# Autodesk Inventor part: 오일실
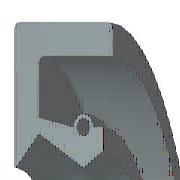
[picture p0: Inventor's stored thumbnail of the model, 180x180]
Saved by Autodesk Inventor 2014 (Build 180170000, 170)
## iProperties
Created: 2009-02
Part Number: 오일실
Material: 고무
Description: 오일-실
Document SubType Name: Modeling
Standard: KS B 2804
Designer: KYOUNG IL JANG
Standards Organization: KS
Language: ko-KR
Size Designation: D - 10 20 7
Categories: <MemberInstance><Categories><Category DisplayName="샤프트 부품" InternalName="7f7aeb1f-a693-4053-b835-cee3144e0d98" Mnemonic="SHFT"><Category DisplayName="실링" Intern
Density: 0.93 g/cm^3
Mass: 1.11329 g
Surface Area: 16.3871 cm^2
Volume: 1.19708 cm^3
Appearance: 고무 - 검은색 - 버전 1.1
Company: 한국ATC센터
IsCustomPart: 0
Author: KYOUNG IL JANG
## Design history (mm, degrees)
revolve "본체" stored, may be unused: angle "d17" = 90 deg
revolve "스프링1" stored, may be unused: angle "d18" = 90 deg
body "Solid1"
sketch "스케치1"
  geometry: L1 (0, 10)-(7, 10); L2 (7, 8.25)-(1.75, 8.25); L3 (1.75, 6.75)-(4.9, 5); L4 (4.9, 5)-(0, 5); L5 (0, 0)-(9.586, 0) reference; L6 (4.9, 5)-(6.3, 5.875); L7 (0, 18)-(0, -3) reference; L8 (-1.941, 0)-(11.507, 0) reference; L9 (4.2, 7.1)-(1.75, 7.59); L10 (1.75, 7.59)-(1.75, 8.25); L11 (0, 10)-(0, 5.088); L12 (4.9, 5)-(0, 5); L13 (1.75, 6.75)-(0.152, 5.028); L14 (7, 10)-(7, 8.25); L15 (5.6, 7.1)-(6.3, 7.1); L16 (6.3, 7.1)-(6.3, 5.875); C1 r 0.455 at (4.9, 7.1); A1 r 0.7 centre (4.9, 7.1) between (5.6, 7.1) and (4.2, 7.1); A2 r 0.088 centre (0.088, 5.088) between (0, 5.088) and (0.152, 5.028); 1 further point
  constraints: 28 end point, 5 horizontal alignment, 5 point on line, 4 point on circle, 4 vertical alignment, 3 centre point, 3 tangent, 2 collinear, 2 horizontal, 2 perpendicular, 1 coincident, 1 parallel
  dimensions: "d0" = 20 diameter of L1 L5 (= SD2); "d1" = 1.75 distance of L1.end L2.start (= SD); "d2" = 0.91 diameter of C1 (= SPDI); "d3" = 1.4 diameter of A1 (= SPDA); "d4" = 10 diameter of L3.end L5 (= NND); "d5" = 13.5 diameter of L3.start L5 (= TKDM); "d7" = 15.18 diameter of L9.end L5 (= TKDM + 0.24 x SWDT); "d8" = 1.75 distance between parallel lines of L11 L10 (= SD); "d9" = 4.9 distance from line of L11 C1.centre (= SPDST); "d10" = 14.2 diameter of C1.centre L5 (= HLDM); "d11" = 0.0875 radius of A2 (= 0.25 x LAB); "d12" = 6.3 distance between parallel lines of L11 L16 (= SDI); "d13" = 11.75 diameter of L6.end L5 (= ABDM); "d14" = 7 distance from line of L11 L1.end (= SWDT)
fillet "모깎기1" dims "d6" = 0.3 (= RR)
other parameters: "SD2" = 20 [user parameter; used in 1 equation term], "SWDT" = 7 [user parameter; used in 2 equation terms], "RR" = 0.3 [user parameter; used in 1 equation term], "SD" = 1.75 [user parameter; used in 2 equation terms], "NND" = 10 [user parameter; used in 1 equation term], "SPDA" = 1.4 [user parameter; used in 1 equation term], "SPDI" = 0.91 [user parameter; used in 1 equation term], "TKDM" = 13.5 [user parameter; used in 2 equation terms], "HLDM" = 14.2 [user parameter; used in 1 equation term], "ABDM" = 11.75 [user parameter; used in 1 equation term], "SDI" = 6.3 [user parameter; used in 1 equation term], "SPDST" = 4.9 [user parameter; used in 1 equation term], "LAB" = 0.35 [user parameter; used in 1 equation term], "d15" = 0, "d16" = 0, "d19" = 0
